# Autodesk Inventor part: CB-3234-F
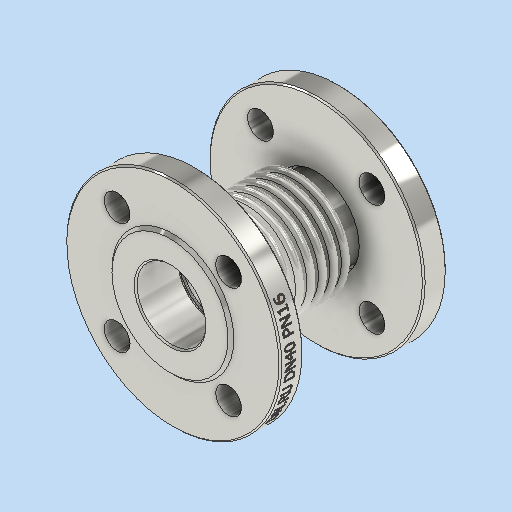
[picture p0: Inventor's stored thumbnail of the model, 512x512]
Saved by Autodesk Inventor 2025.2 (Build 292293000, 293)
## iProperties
Company: DN.RU
Created: 2026-04
Part Number: CB-3234-F
Material: Типовые
Document SubType Name: Modeling
Designer: DN.RU
Density: 7.12573 g/cm^3
Appearance: По умолчанию
Description: D140-02112
Mass: 3800 g
Surface Area: 1708.59 cm^2
Volume: 533.279 cm^3
Author: DN.RU
Title: Компенсатор сильфонный осевой DN.ru Ду40 Ру16
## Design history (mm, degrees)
sketch "Эскиз1"
  geometry: L1 (0, 0)-(0, -60); L2 (28, -60)-(28, 0); L3 (28, 0)-(0, 0); L4 (28, 0)-(28, -4); L5 (22, -4)-(34, -4); L6 (22, -6.5)-(34, -6.5); L7 (34, -1.5)-(22, -1.5); L8 (34, -5.5)-(22, -5.5); L9 (22, -2.5)-(34, -2.5); L10 (34, -9.5)-(22, -9.5); L11 (22, -10.5)-(34, -10.5); L12 (22, -12)-(34, -12); L13 (22, -14.5)-(34, -14.5); L14 (34, -13.5)-(22, -13.5); L15 (34, -17.5)-(22, -17.5); L16 (22, -18.5)-(34, -18.5); L17 (22, -20)-(34, -20); L18 (22, -22.5)-(34, -22.5); L19 (34, -21.5)-(22, -21.5); L20 (34, -25.5)-(22, -25.5); L21 (22, -26.5)-(34, -26.5); L22 (22, -28)-(34, -28); L23 (22, -30.5)-(34, -30.5); L24 (34, -29.5)-(22, -29.5); L25 (0, -60)-(28, -60); L26 (28, -60)-(24, -60); L27 (28, -25.5)-(27, -25.5); L28 (24, -60)-(24, -29.5); L29 (28, -26.5)-(27, -26.5); L30 (27, -26.5)-(27, -21.5); L31 (28, -18.5)-(27, -18.5); L32 (27, -18.5)-(27, -13.5); L33 (28, -10.5)-(27, -10.5); L34 (27, -10.5)-(27, -5.5); L35 (28, -2.5)-(27, -2.5); L36 (27, -2.5)-(27, 0); L37 (0, -60)-(0, -42); L38 (0, -42)-(75, -42); L39 (75, -42)-(75, -60); L40 (75, -60)-(0, -60); L41 (28, -42)-(28, -52); L42 (28, -52)-(30, -52); L43 (30, -52)-(30, -42); L44 (30, -42)-(28, -42); A1 r 2.5 centre (22, -4) between (22, -1.5) and (22, -6.5); A2 r 2.5 centre (34, -4) between (34, -6.5) and (34, -1.5); A3 r 1.5 centre (22, -4) between (22, -2.5) and (22, -5.5); A4 r 1.5 centre (34, -4) between (34, -5.5) and (34, -2.5); A5 r 1.5 centre (22, -12) between (22, -10.5) and (22, -13.5); A6 r 2.5 centre (22, -12) between (22, -9.5) and (22, -14.5); A7 r 1.5 centre (34, -12) between (34, -13.5) and (34, -10.5); A8 r 2.5 centre (34, -12) between (34, -14.5) and (34, -9.5); A9 r 1.5 centre (22, -20) between (22, -18.5) and (22, -21.5); A10 r 2.5 centre (22, -20) between (22, -17.5) and (22, -22.5); A11 r 1.5 centre (34, -20) between (34, -21.5) and (34, -18.5); A12 r 2.5 centre (34, -20) between (34, -22.5) and (34, -17.5); A13 r 1.5 centre (22, -28) between (22, -26.5) and (22, -29.5); A14 r 2.5 centre (22, -28) between (22, -25.5) and (22, -30.5); A15 r 1.5 centre (34, -28) between (34, -29.5) and (34, -26.5); A16 r 2.5 centre (34, -28) between (34, -30.5) and (34, -25.5); 20 further points
  constraints: 96 end point, 32 point on circle, 19 point on line, 16 centre point, 7 parallel, 7 perpendicular, 6 midpoint, 4 tangent, 2 vertical, 1 horizontal, 69 other
  dimensions: "d0" = 60 distance of L1.start L1.end; "d3" = 4 distance of L2.end L4.end; "d4" = 6 distance of L4.end L5.end; "d5" = 5 diameter of A2; "d6" = 1 distance between parallel lines of L6 L8; "d9" = 8 distance of L4.end point (28, -12); "d15" = 1 distance of L27.start L27.end; "d16" = 1 distance of L29.start L29.end; "d17" = 1 distance of L31.start L31.end; "d18" = 1 distance of L33.start L33.end; "d19" = 1 distance of L35.start L35.end; "d27" = 24 distance between parallel lines of L1 L28; "d28" = 4 distance between parallel lines of L2 L28; "d29" = 18 distance of L1.end L37.end; "d30" = 75 distance of L37.end L38.end; "d31" = 10 distance of L41.start L41.end; "d32" = 2 distance of L42.end L41.end
revolve "Вращение1" sketch "Эскиз1" stored, may be unused: angle "d20" = 360 deg
sketch "Эскиз3" dims "d33" = 110
  geometry: L1 (0, 0)-(54.414, 54.414); L2 (0, 0)-(76.954, 0); C1 r 9 at (38.891, 38.891); C2 r 9 at (-38.891, 38.891); C3 r 9 at (-38.891, -38.891); C4 r 9 at (38.891, -38.891); C5 r 24 at (0, 0) reference; C6 r 42.5 at (0, 0); C7 r 75 at (0, 0) reference; 1 further point
  constraints: 5 centre point, 4 end point, 2 coincident, 1 equal length, 1 horizontal, 1 point on line, 12 other
  dimensions: "d34" = 45 deg angle of L2 L1; "d35" = 18 diameter of C1; "d38" = 360 deg dimension on point (0, 0) C1.centre (derived); "d40" = 85 diameter of C6
  node "Эскиз — круговой массив1" dims "d38" = 360 deg (derived)
extrude "Выдавливание1" cut sketch "Эскиз3" stored distance "d41" = 10; taper "d42" = 0 deg
extrude "Выдавливание2" cut sketch "Эскиз3" distance "d43" = 2; taper "d44" = 0 deg
chamfer "Фаска2" distance "d45" = 2; stored, may be unused: second distance "d46" = 2, angle "d47" = 45 deg
chamfer "Фаска3" distance "d48" = 1; stored, may be unused: second distance "d49" = 2, angle "d50" = 45 deg
mirror "Зеркальное отражение2"
fillet "Сопряжение2" dims "d51" = 1
node "РабПлоскость2"
sketch "Эскиз4"
  geometry: L1 (-44.383, 3.589)-(46.395, 3.589); L2 (46.395, 3.589)-(46.395, 0.413); L3 (46.395, 0.413)-(-44.383, 0.413); L4 (-44.383, 0.413)-(-44.383, 3.589); 1 further point
  constraints: 2 other
feature "Рельеф2" sketch "Эскиз4" dims "d52" = 0.1, "d53" = 0
node "Твердое тело1"
node "Эскиз — прямоугольный массив1" dims "d9" = 8, "d12" = 10
